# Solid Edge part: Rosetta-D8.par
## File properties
Title: 1320701090
Subject: Rosetta comune x vite M8
Author: g_deluca
Template: RBuno.par
Last saved by: f_grande
Revision: 14
Application: Solid Edge
Company: EFFEBI S.p.A.
Codice: Codice
Indice rev.: Rev.
Data rev.: Data rev.
Firma rev.: Firma rev.
Descrizione rev.: Descrizione rev.
Densità: 7860,000 kg/m^3
Precisione: 0,99
Tipo di contenuto documento: 0
Document Number: UNI 6592
Material: Ccasse R40
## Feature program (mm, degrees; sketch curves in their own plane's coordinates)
sketch for "unnamed Protrusion 1" #1 plane through (0, 0, 0) normal (0, 0, 1) x-axis (1, 0, 0)
sketch for "unnamed Protrusion 1" #2 plane through (0, 0, 0) normal (0, 0, 1) x-axis (1, 0, 0)
extrude "unnamed Protrusion 1" add finite 1.6 along -normal
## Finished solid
Body 1: solid body, 4 faces, 4 edges, 0 vertices.
  Faces by surface: cylinder 2, plane 2
  Edges by curve: circle 4
Bounding box of the edges (mm): 17.000 x 17.000 x 1.600, from (-8.5, -8.5, -1.6) to (8.5, 8.5, 0).
Cylindrical faces by radius (mm): R4.2 x1, R8.5 x1
Planar faces by outward normal: +z 1, -z 1
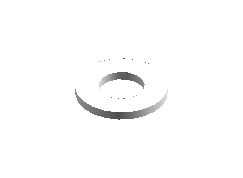
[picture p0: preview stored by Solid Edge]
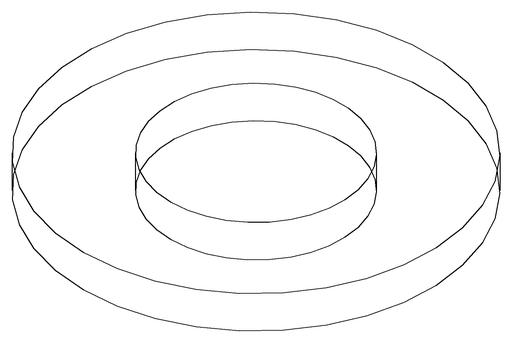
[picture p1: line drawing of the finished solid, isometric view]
